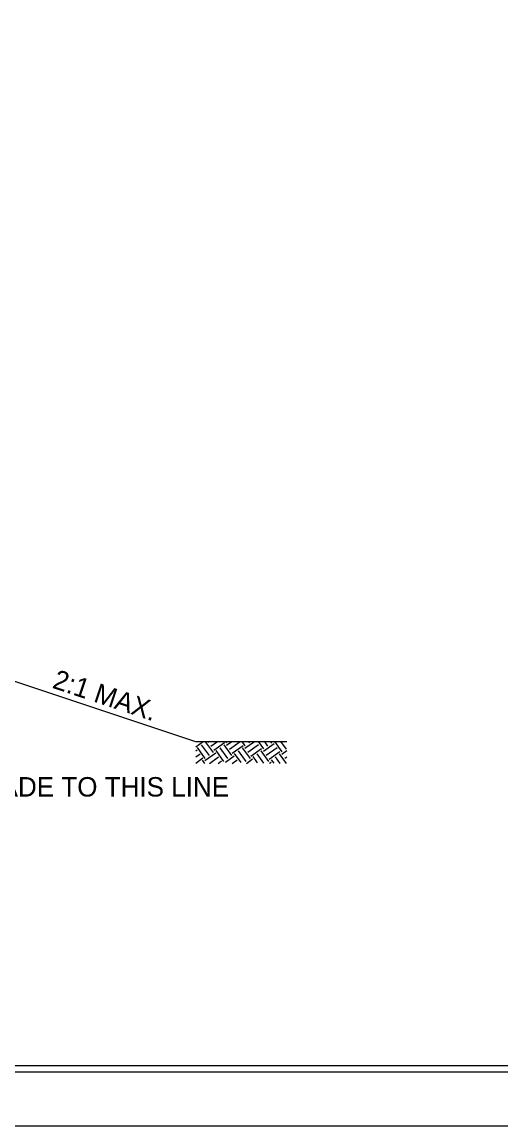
# Model space of a CAD drawing. Extents: x 3025871 to 3026431, y 707165 to 707825.
# Drawn here: x 3026184.6 to 3026214.4, y 707397.1 to 707465.6 of the extents above; entities that cross this region are included whole.
import ezdxf

# ---------------------------------------------------------------- set-up
doc = ezdxf.new("R2010")
doc.units = 0
for name, color, linetype in [('Old_Level_39', 7, 'Continuous'), ('Prop Drainage Structure Junction Box with Slab Lid TB 840 34 CELL', 7, 'Continuous'), ('Sheet Cutting Line CELL', 7, 'Continuous'), ('Typical Terminator CELL', 7, 'Continuous'), ('Typical Text Grade Point CELL', 7, 'Continuous')]:
    doc.layers.add(name, color=color, linetype=linetype)

msp = doc.modelspace()

# ---------------------------------------------------------------- linework, layer by layer
at = {"layer": 'Old_Level_39'}
msp.add_lwpolyline([(3026273.948, 707558.686), (3026023.973, 707558.686), (3026023.973, 707400.421), (3026273.948, 707400.421)], close=True, dxfattribs=at)
at = {"layer": 'Sheet Cutting Line CELL'}
msp.add_lwpolyline([(3026272.073, 707558.304), (3026047.073, 707558.304), (3026047.073, 707400.804), (3026272.073, 707400.804)], close=True, dxfattribs=at)
at = {"layer": 'Typical Terminator CELL'}
msp.add_lwpolyline([(3026274.623, 707562.054), (3026022.023, 707562.054), (3026022.023, 707397.054), (3026274.623, 707397.054)], close=True, dxfattribs=at)
at = {"layer": 'Typical Text Grade Point CELL'}
for p, q in [((3026182.416, 707425.276), (3026195.416, 707420.942)), ((3026195.416, 707420.942), (3026201.1, 707420.942)), ((3026195.416, 707420.942), (3026201.1, 707420.942)), ((3026195.437, 707420.613), (3026195.897, 707420.943)), ((3026195.437, 707420.613), (3026195.897, 707420.943)), ((3026196.026, 707419.896), (3026195.546, 707420.564)), ((3026196.026, 707419.896), (3026195.546, 707420.564)), ((3026196.277, 707420.076), (3026195.796, 707420.744)), ((3026196.277, 707420.076), (3026195.796, 707420.744)), ((3026196.527, 707420.256), (3026196.047, 707420.925)), ((3026196.527, 707420.256), (3026196.047, 707420.925)), ((3026196.191, 707420.901), (3026196.251, 707420.944)), ((3026196.191, 707420.901), (3026196.251, 707420.944)), ((3026196.371, 707420.65), (3026196.782, 707420.946)), ((3026196.371, 707420.65), (3026196.782, 707420.946)), ((3026196.551, 707420.4), (3026197.219, 707420.88)), ((3026196.551, 707420.4), (3026197.219, 707420.88)), ((3026197.426, 707419.888), (3026196.945, 707420.556)), ((3026197.426, 707419.888), (3026196.945, 707420.556)), ((3026197.676, 707420.068), (3026197.196, 707420.736)), ((3026197.676, 707420.068), (3026197.196, 707420.736)), ((3026197.363, 707420.857), (3026197.298, 707420.947)), ((3026197.363, 707420.857), (3026197.298, 707420.947)), ((3026197.339, 707420.713), (3026197.667, 707420.948)), ((3026197.339, 707420.713), (3026197.667, 707420.948)), ((3026197.52, 707420.462), (3026198.188, 707420.943)), ((3026197.52, 707420.462), (3026198.188, 707420.943)), ((3026197.7, 707420.212), (3026198.368, 707420.692)), ((3026197.7, 707420.212), (3026198.368, 707420.692)), ((3026198.512, 707420.668), (3026198.309, 707420.95)), ((3026198.512, 707420.668), (3026198.309, 707420.95)), ((3026198.825, 707419.88), (3026198.345, 707420.548)), ((3026198.825, 707419.88), (3026198.345, 707420.548)), ((3026198.488, 707420.525), (3026199.083, 707420.952)), ((3026198.488, 707420.525), (3026199.083, 707420.952)), ((3026198.668, 707420.274), (3026199.337, 707420.755)), ((3026198.668, 707420.274), (3026199.337, 707420.755)), ((3026198.762, 707420.849), (3026198.688, 707420.951)), ((3026198.762, 707420.849), (3026198.688, 707420.951)), ((3026199.66, 707420.48), (3026199.328, 707420.942)), ((3026199.66, 707420.48), (3026199.328, 707420.942)), ((3026199.637, 707420.337), (3026200.305, 707420.817)), ((3026199.637, 707420.337), (3026200.305, 707420.817)), ((3026199.911, 707420.661), (3026199.7, 707420.954)), ((3026199.911, 707420.661), (3026199.7, 707420.954)), ((3026199.817, 707420.086), (3026200.485, 707420.566)), ((3026199.817, 707420.086), (3026200.485, 707420.566)), ((3026200.162, 707420.841), (3026200.089, 707420.942)), ((3026200.162, 707420.841), (3026200.089, 707420.942)), ((3026200.809, 707420.292), (3026200.342, 707420.942)), ((3026200.809, 707420.292), (3026200.342, 707420.942)), ((3026201.06, 707420.472), (3026200.722, 707420.942)), ((3026201.06, 707420.472), (3026200.722, 707420.942)), ((3026195.437, 707420.36), (3026195.522, 707420.421)), ((3026195.437, 707420.36), (3026195.522, 707420.421)), ((3026195.437, 707419.979), (3026195.702, 707420.17)), ((3026195.437, 707419.979), (3026195.702, 707420.17)), ((3026195.437, 707419.599), (3026195.883, 707419.919)), ((3026195.437, 707419.599), (3026195.883, 707419.919)), ((3026196.003, 707419.752), (3026196.671, 707420.233)), ((3026196.003, 707419.752), (3026196.671, 707420.233)), ((3026196.295, 707419.582), (3026196.851, 707419.982)), ((3026196.295, 707419.582), (3026196.851, 707419.982)), ((3026197.175, 707419.708), (3026196.695, 707420.376)), ((3026197.175, 707419.708), (3026196.695, 707420.376)), ((3026197.271, 707419.65), (3026197.82, 707420.045)), ((3026197.271, 707419.65), (3026197.82, 707420.045)), ((3026198.244, 707419.631), (3026197.843, 707420.188)), ((3026198.244, 707419.631), (3026197.843, 707420.188)), ((3026198.574, 707419.7), (3026198.094, 707420.368)), ((3026198.574, 707419.7), (3026198.094, 707420.368)), ((3026198.587, 707419.582), (3026198.968, 707419.856)), ((3026198.587, 707419.582), (3026198.968, 707419.856)), ((3026198.848, 707420.024), (3026199.517, 707420.504)), ((3026198.848, 707420.024), (3026199.517, 707420.504)), ((3026199.272, 707419.61), (3026198.992, 707420)), ((3026199.272, 707419.61), (3026198.992, 707420)), ((3026199.658, 707419.602), (3026199.243, 707420.18)), ((3026199.658, 707419.602), (3026199.243, 707420.18)), ((3026199.974, 707419.692), (3026199.493, 707420.36)), ((3026199.974, 707419.692), (3026199.493, 707420.36)), ((3026199.997, 707419.836), (3026200.666, 707420.316)), ((3026199.997, 707419.836), (3026200.666, 707420.316)), ((3026200.686, 707419.582), (3026200.391, 707419.992)), ((3026200.686, 707419.582), (3026200.391, 707419.992)), ((3026201.072, 707419.574), (3026200.642, 707420.172)), ((3026201.072, 707419.574), (3026200.642, 707420.172)), ((3026200.786, 707420.149), (3026201.1, 707420.375)), ((3026200.786, 707420.149), (3026201.1, 707420.375)), ((3026200.966, 707419.898), (3026201.1, 707419.995)), ((3026200.966, 707419.898), (3026201.1, 707419.995)), ((3026195.998, 707419.582), (3026195.859, 707419.776)), ((3026195.998, 707419.582), (3026195.859, 707419.776)), ((3026196.824, 707419.582), (3026197.031, 707419.731)), ((3026196.824, 707419.582), (3026197.031, 707419.731)), ((3026197.705, 707419.582), (3026198, 707419.794)), ((3026197.705, 707419.582), (3026198, 707419.794)), ((3026200.015, 707419.595), (3026200.117, 707419.668)), ((3026200.015, 707419.595), (3026200.117, 707419.668)), ((3026200.301, 707419.589), (3026200.141, 707419.812)), ((3026200.301, 707419.589), (3026200.141, 707419.812))]:
    msp.add_line(p, q, dxfattribs=at)

# ---------------------------------------------------------------- texts
at = {"layer": 'Prop Drainage Structure Junction Box with Slab Lid TB 840 34 CELL'}
msp.add_text('GRADE TO THIS LINE', height=1.20892, dxfattribs=at).set_placement((3026180.886, 707417.521))
at = {"layer": 'Typical Text Grade Point CELL'}
msp.add_text('2:1 MAX.', height=1.2089, rotation=341.56505, dxfattribs=at).set_placement((3026186.468, 707424.292))

doc.saveas('drawing.dxf')
